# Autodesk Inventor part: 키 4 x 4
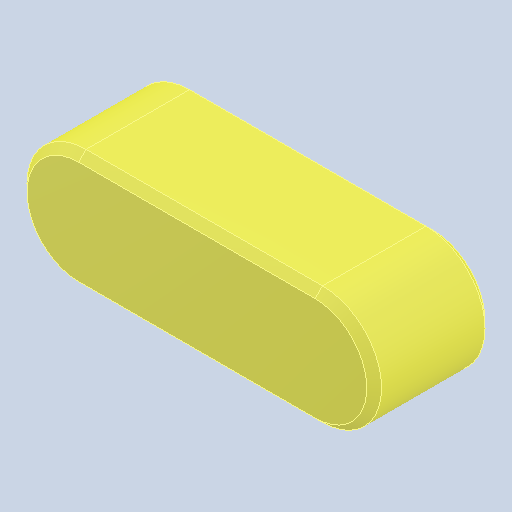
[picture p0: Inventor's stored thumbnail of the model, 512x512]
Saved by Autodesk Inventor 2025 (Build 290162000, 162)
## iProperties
Created: 2025-08
Part Number: 키 4 x 4
Material: 강철, 연강
Description: 키 및 해당 키홈
Document SubType Name: Modeling
Designer: infra04
Density: 7.86 g/cm^3
Appearance: 기본값
Author: jhkim
Sending System: Autodesk Inventor 2026
Preprocessor: ST-DEVELOPER v20.1
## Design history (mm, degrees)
feature "Solid1"
node "솔리드1"
